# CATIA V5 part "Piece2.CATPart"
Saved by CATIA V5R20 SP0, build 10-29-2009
Part number: Piece2
Bounding box of the stored display mesh (mm): x 0 to 20, y -16.358 to 31.305, z -18.726 to 28.168
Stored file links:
  C:\Users\ASUS\Desktop\Think Motion IAO\Piece2.CATPart
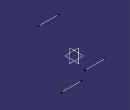
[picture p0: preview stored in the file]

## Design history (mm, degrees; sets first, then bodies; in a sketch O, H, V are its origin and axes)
Body1 (main body)
  Point1 "Point.O": stored without definition
  Line1: type PtDir, RefPoint Point1, Direction yz-plane, Start 0, End 20
  Point2 "Point.D": stored without definition
  Line2: type PtDir, RefPoint Point2, Direction yz-plane, Start 0, End 20
  Point3 "Point.B": stored without definition
  Line3: type PtDir, RefPoint Point3, Direction yz-plane, Start 0, End 20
